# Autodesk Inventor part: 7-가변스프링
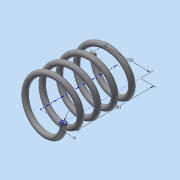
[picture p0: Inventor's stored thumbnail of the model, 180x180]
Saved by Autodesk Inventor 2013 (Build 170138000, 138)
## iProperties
Created: 2015-03
Part Number: 7-가변스프링
Material: 강철, 탄소
Document SubType Name: Modeling
Designer: Administrator
Density: 7.87 g/cm^3
Mass: 48.2733 g
Surface Area: 62.0009 cm^2
Volume: 6.13384 cm^3
Author: Administrator
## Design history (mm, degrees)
sketch "스케치1"
  geometry: L1 (0, 0)-(17.5, 0); L2 (17.5, 0)-(17.5, 43.5); L3 (17.5, 43.5)-(0, 43.5); L4 (0, 43.5)-(0, 0); C1 r 2 at (17.5, 0)
  constraints: 8 end point, 2 parallel, 1 centre point, 1 coincident, 1 horizontal, 1 perpendicular
  dimensions: "d0" = 43.5 distance of L1.end L2.end (derived); "d2" = 35 diameter of L2 L4; "d3" = 4 diameter of C1
feature "코일1" sketch "스케치1" pitch "d4" = 10; turns "d6" = 4.5; dims "d5" = 43.5 (= d0), "d7" = 0, angle "d8" = 90 deg, angle "d9" = 90 deg, "d10" = 0, "d11" = 0
node "작업 평면1"
sketch "스케치2"
  geometry: L1 (-19.5, 0)-(-15.5, 0) reference; 1 further point
  constraints: 1 horizontal alignment
extrude "돌출1" cut sketch "스케치2" stored distance "d13" = 10; taper "d14" = 0 deg
node "작업 평면2"
sketch "스케치3"
  geometry: L1 (-19.5, 0)-(-15.5, 0) reference; 1 further point
  constraints: 1 horizontal alignment
extrude "돌출2" cut sketch "스케치3" stored distance "d16" = 10; taper "d17" = 0 deg
node "솔리드1"
node "절단 모서리 투영1"
node "절단 모서리 투영2"
other parameters: "d12" = 0, "d15" = -43.5 (= -d0)
